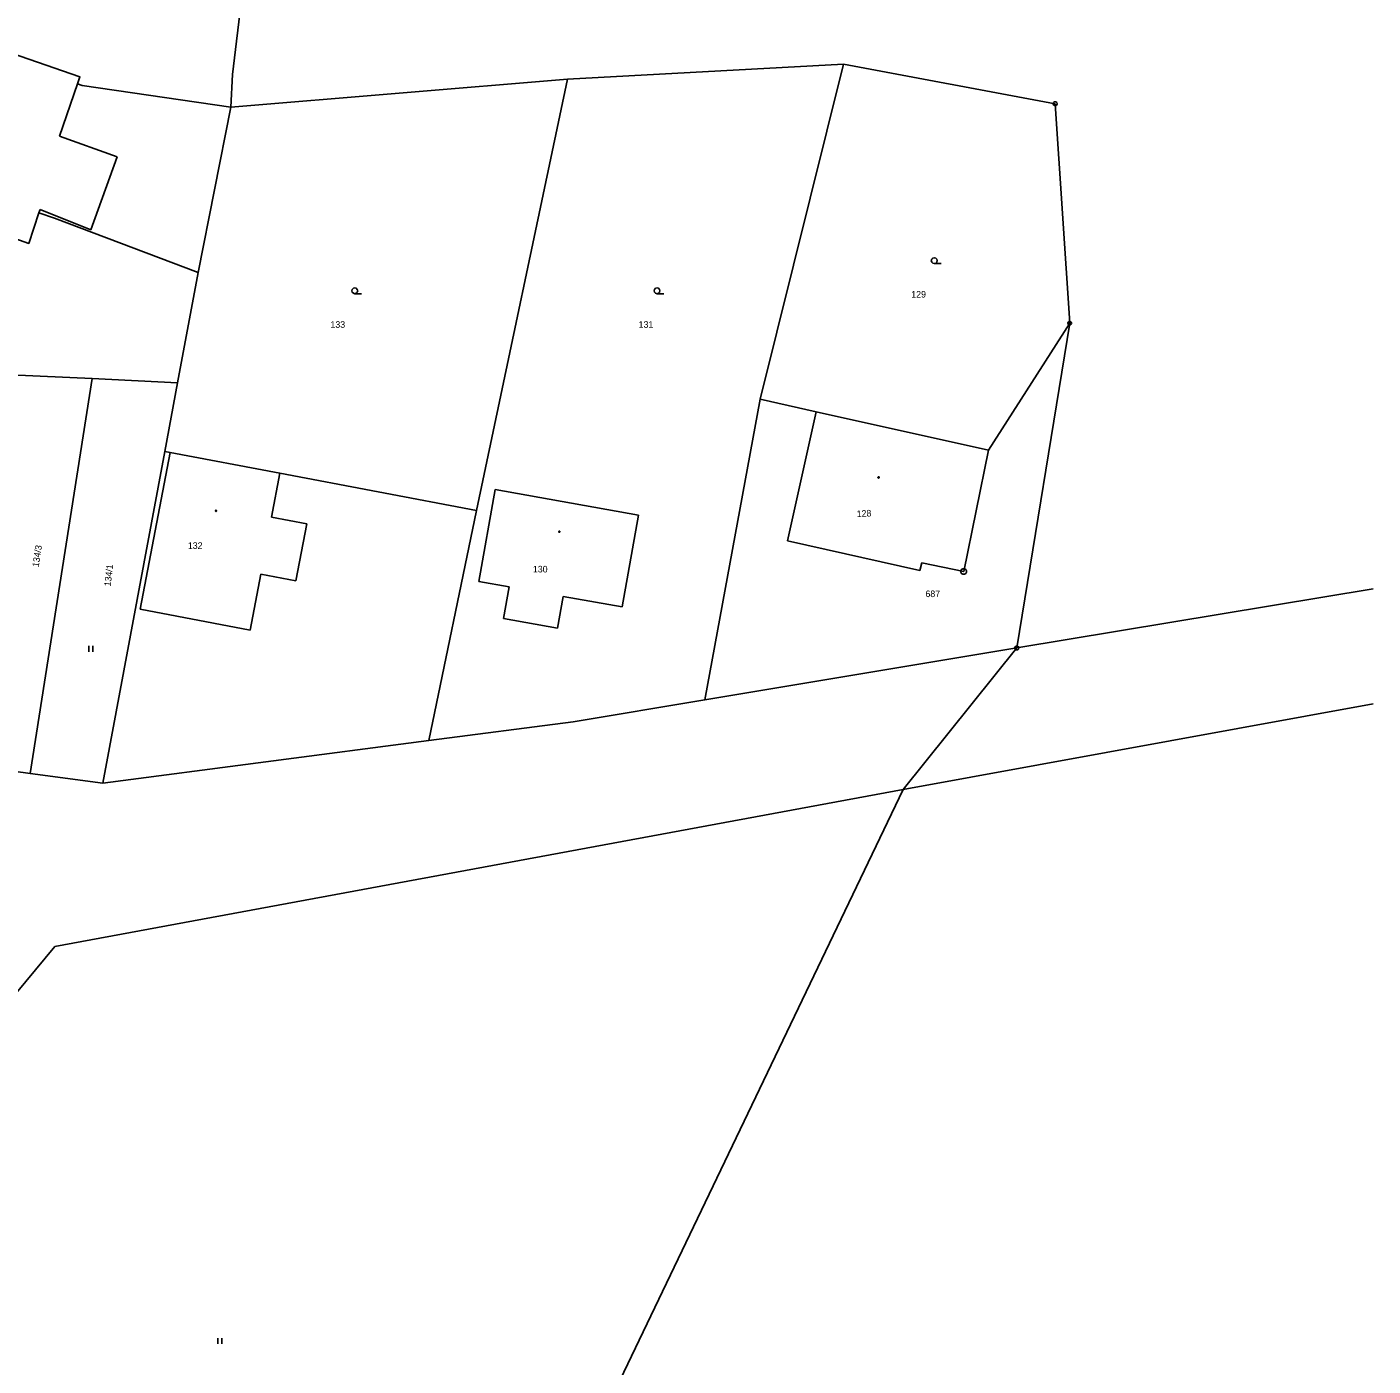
# Model space of a CAD drawing. Extents: x -871430 to -870620, y -1010094 to -1009649.
# Drawn here: x -870707.3 to -870620.4, y -1009951.2 to -1009864.8 of the extents above; entities that cross this region are included whole.
import ezdxf

# ---------------------------------------------------------------- set-up
doc = ezdxf.new("R2010")
doc.units = 0
for name, color, linetype in [('Vrstva 1', 7, 'Continuous'), ('Vrstva 2', 7, 'Continuous'), ('Vrstva 3', 7, 'Continuous'), ('Vrstva 4', 7, 'Continuous'), ('Vrstva 5', 7, 'Continuous'), ('Vrstva 8', 7, 'Continuous')]:
    doc.layers.add(name, color=color, linetype=linetype)

msp = doc.modelspace()

# ---------------------------------------------------------------- linework, layer by layer
at = {"layer": 'Vrstva 1'}
for p, q in [((-870694.01, -1009867.87), (-870689.91, -1009833.79)), ((-870654.6, -1009867.19), (-870672.41, -1009868.17)), ((-870654.6, -1009867.19), (-870659.97, -1009888.82)), ((-870640.94, -1009869.75), (-870654.6, -1009867.19)), ((-870694.11, -1009869.96), (-870694.01, -1009867.87)), ((-870672.41, -1009868.17), (-870694.11, -1009869.96)), ((-870672.41, -1009868.17), (-870678.28, -1009896.01)), ((-870703.72, -1009868.57), (-870704.01, -1009868.47)), ((-870703.72, -1009868.57), (-870694.11, -1009869.96)), ((-870694.11, -1009869.96), (-870696.22, -1009880.64)), ((-870640, -1009883.91), (-870640.94, -1009869.75)), ((-870706.5, -1009876.79), (-870705.5, -1009877.14)), ((-870705.5, -1009877.14), (-870696.22, -1009880.64)), ((-870696.22, -1009880.64), (-870697.55, -1009887.76)), ((-870645.25, -1009892.11), (-870640, -1009883.91)), ((-870643.41, -1009904.87), (-870640, -1009883.91)), ((-870708.34, -1009887.24), (-870703.07, -1009887.49)), ((-870703.07, -1009887.49), (-870707.06, -1009912.97)), ((-870703.07, -1009887.49), (-870697.55, -1009887.76)), ((-870697.55, -1009887.76), (-870698.38, -1009892.2)), ((-870659.97, -1009888.82), (-870663.53, -1009908.22)), ((-870659.97, -1009888.82), (-870656.35, -1009889.63)), ((-870656.35, -1009889.63), (-870645.25, -1009892.11)), ((-870698.38, -1009892.2), (-870702.37, -1009913.6)), ((-870698.38, -1009892.2), (-870698.04, -1009892.26)), ((-870698.04, -1009892.26), (-870690.95, -1009893.6)), ((-870690.95, -1009893.6), (-870678.28, -1009896.01)), ((-870677.07, -1009894.65), (-870678.13, -1009900.58)), ((-870677.07, -1009894.65), (-870667.82, -1009896.3)), ((-870678.28, -1009896.01), (-870681.34, -1009910.85)), ((-870667.82, -1009896.3), (-870668.88, -1009902.23)), ((-870678.13, -1009900.58), (-870676.16, -1009900.93)), ((-870676.16, -1009900.93), (-870676.52, -1009902.98)), ((-870620.429, -1009901.068), (-870643.41, -1009904.87)), ((-870672.68, -1009901.55), (-870673.04, -1009903.59)), ((-870672.68, -1009901.55), (-870668.88, -1009902.23)), ((-870676.52, -1009902.98), (-870673.04, -1009903.59)), ((-870663.53, -1009908.22), (-870643.41, -1009904.87)), ((-870650.74, -1009914), (-870643.41, -1009904.87)), ((-870672.03, -1009909.64), (-870663.53, -1009908.22)), ((-870650.74, -1009914), (-870620.429, -1009908.484)), ((-870681.34, -1009910.85), (-870672.03, -1009909.64)), ((-870702.37, -1009913.6), (-870681.34, -1009910.85)), ((-870709.66, -1009912.62), (-870707.06, -1009912.97)), ((-870707.06, -1009912.97), (-870702.37, -1009913.6)), ((-870650.74, -1009914), (-870705.48, -1009924.14)), ((-870683.39, -1009982.15), (-870650.74, -1009914)), ((-870705.48, -1009924.14), (-870713.4, -1009933.7))]:
    msp.add_line(p, q, dxfattribs=at)
msp.add_lwpolyline([(-870704.01, -1009868.47), (-870703.85, -1009868.01), (-870712.63, -1009864.98), (-870715.68, -1009873.77), (-870709.31, -1009875.99), (-870709.95, -1009877.77), (-870707.16, -1009878.76), (-870706.5, -1009876.79)], dxfattribs=at)
at = {"layer": 'Vrstva 3'}
for p, q in [((-870703.275, -1009904.745), (-870703.275, -1009905.12)), ((-870703.025, -1009905.12), (-870703.025, -1009904.745)), ((-870694.955, -1009949.415), (-870694.955, -1009949.79)), ((-870694.705, -1009949.79), (-870694.705, -1009949.415))]:
    msp.add_line(p, q, dxfattribs=at)
for points in [[(-870648.74, -1009880.06), (-870648.835, -1009880.035), (-870648.902, -1009879.965), (-870648.928, -1009879.872), (-870648.902, -1009879.78), (-870648.835, -1009879.71), (-870648.74, -1009879.685), (-870648.645, -1009879.71), (-870648.578, -1009879.78), (-870648.552, -1009879.872), (-870648.578, -1009879.965), (-870648.645, -1009880.035), (-870648.74, -1009880.06), (-870648.302, -1009880.06)], [(-870686.12, -1009882.01), (-870686.215, -1009881.985), (-870686.282, -1009881.915), (-870686.308, -1009881.822), (-870686.282, -1009881.73), (-870686.215, -1009881.66), (-870686.12, -1009881.635), (-870686.025, -1009881.66), (-870685.958, -1009881.73), (-870685.932, -1009881.822), (-870685.958, -1009881.915), (-870686.025, -1009881.985), (-870686.12, -1009882.01), (-870685.682, -1009882.01)], [(-870666.62, -1009882.01), (-870666.715, -1009881.985), (-870666.782, -1009881.915), (-870666.808, -1009881.822), (-870666.782, -1009881.73), (-870666.715, -1009881.66), (-870666.62, -1009881.635), (-870666.525, -1009881.66), (-870666.458, -1009881.73), (-870666.432, -1009881.822), (-870666.458, -1009881.915), (-870666.525, -1009881.985), (-870666.62, -1009882.01), (-870666.182, -1009882.01)]]:
    msp.add_lwpolyline(points, dxfattribs=at)
at = {"layer": 'Vrstva 4'}
for p, q in [((-870704.01, -1009868.47), (-870705.18, -1009871.84)), ((-870705.18, -1009871.84), (-870701.46, -1009873.18)), ((-870701.46, -1009873.18), (-870703.15, -1009877.88)), ((-870706.5, -1009876.79), (-870706.43, -1009876.57)), ((-870703.15, -1009877.88), (-870706.43, -1009876.57)), ((-870658.21, -1009897.97), (-870656.35, -1009889.63)), ((-870699.96, -1009902.38), (-870698.04, -1009892.26)), ((-870645.25, -1009892.11), (-870646.84, -1009899.94)), ((-870690.95, -1009893.6), (-870691.49, -1009896.43)), ((-870689.22, -1009896.86), (-870691.49, -1009896.43)), ((-870689.92, -1009900.55), (-870689.22, -1009896.86)), ((-870649.66, -1009899.87), (-870658.21, -1009897.97)), ((-870649.55, -1009899.39), (-870649.66, -1009899.87)), ((-870646.84, -1009899.94), (-870649.55, -1009899.39)), ((-870692.19, -1009900.12), (-870692.87, -1009903.72)), ((-870692.19, -1009900.12), (-870689.92, -1009900.55)), ((-870692.87, -1009903.72), (-870699.96, -1009902.38))]:
    msp.add_line(p, q, dxfattribs=at)
at = {"layer": 'Vrstva 5'}
for points in [[(-870652.326, -1009893.828), (-870652.301, -1009893.835), (-870652.291, -1009893.859), (-870652.288, -1009893.874), (-870652.295, -1009893.896), (-870652.317, -1009893.912), (-870652.334, -1009893.912), (-870652.356, -1009893.902), (-870652.369, -1009893.886), (-870652.372, -1009893.866), (-870652.365, -1009893.844), (-870652.343, -1009893.828), (-870652.326, -1009893.828)], [(-870695.08, -1009895.978), (-870695.055, -1009895.982), (-870695.042, -1009896.005), (-870695.038, -1009896.02), (-870695.042, -1009896.042), (-870695.062, -1009896.06), (-870695.08, -1009896.062), (-870695.102, -1009896.055), (-870695.117, -1009896.04), (-870695.122, -1009896.02), (-870695.117, -1009895.998), (-870695.097, -1009895.98), (-870695.08, -1009895.978)], [(-870672.93, -1009897.328), (-870672.905, -1009897.332), (-870672.893, -1009897.355), (-870672.888, -1009897.37), (-870672.893, -1009897.392), (-870672.913, -1009897.41), (-870672.93, -1009897.412), (-870672.952, -1009897.405), (-870672.968, -1009897.39), (-870672.972, -1009897.37), (-870672.968, -1009897.348), (-870672.948, -1009897.33), (-870672.93, -1009897.328)]]:
    msp.add_lwpolyline(points, dxfattribs=at)
at = {"layer": 'Vrstva 8'}
for p, q in [((-870640.952, -1009869.75), (-870640.928, -1009869.75)), ((-870640.012, -1009883.91), (-870639.988, -1009883.91)), ((-870646.852, -1009899.94), (-870646.828, -1009899.94)), ((-870643.422, -1009904.87), (-870643.398, -1009904.87))]:
    msp.add_line(p, q, dxfattribs=at)
for points in [[(-870640.902, -1009869.63), (-870640.84, -1009869.678), (-870640.815, -1009869.75), (-870640.84, -1009869.822), (-870640.902, -1009869.87), (-870640.977, -1009869.87), (-870641.04, -1009869.822), (-870641.065, -1009869.75), (-870641.04, -1009869.678), (-870640.977, -1009869.63), (-870640.902, -1009869.63)], [(-870639.962, -1009883.79), (-870639.9, -1009883.838), (-870639.875, -1009883.91), (-870639.9, -1009883.982), (-870639.962, -1009884.03), (-870640.038, -1009884.03), (-870640.1, -1009883.982), (-870640.125, -1009883.91), (-870640.1, -1009883.838), (-870640.038, -1009883.79), (-870639.962, -1009883.79)], [(-870646.792, -1009899.76), (-870646.708, -1009899.808), (-870646.66, -1009899.892), (-870646.66, -1009899.99), (-870646.708, -1009900.075), (-870646.792, -1009900.122), (-870646.89, -1009900.122), (-870646.975, -1009900.075), (-870647.022, -1009899.99), (-870647.022, -1009899.892), (-870646.975, -1009899.808), (-870646.89, -1009899.76), (-870646.792, -1009899.76)], [(-870643.372, -1009904.75), (-870643.31, -1009904.798), (-870643.285, -1009904.87), (-870643.31, -1009904.942), (-870643.372, -1009904.99), (-870643.448, -1009904.99), (-870643.51, -1009904.942), (-870643.535, -1009904.87), (-870643.51, -1009904.798), (-870643.448, -1009904.75), (-870643.372, -1009904.75)]]:
    msp.add_lwpolyline(points, dxfattribs=at)

# ---------------------------------------------------------------- texts
at = {"layer": 'Vrstva 2'}
for s, p in [('129', (-870650.222, -1009882.26)), ('133', (-870687.692, -1009884.21)), ('131', (-870667.812, -1009884.21)), ('132', (-870696.892, -1009898.48)), ('130', (-870674.632, -1009900))]:
    msp.add_text(s, height=0.425, dxfattribs=at).set_placement(p)
for s, rotation, p in [('128', 3.32316, (-870653.732, -1009896.434)), ('134/3', 81.36001, (-870706.514, -1009899.675)), ('134/1', 83.53725, (-870701.87, -1009900.918))]:
    msp.add_text(s, height=0.425, rotation=rotation, dxfattribs=at).set_placement(p)
at = {"layer": 'Vrstva 8'}
msp.add_text('687', height=0.425, dxfattribs=at).set_placement((-870649.307, -1009901.592))

doc.saveas('drawing.dxf')
